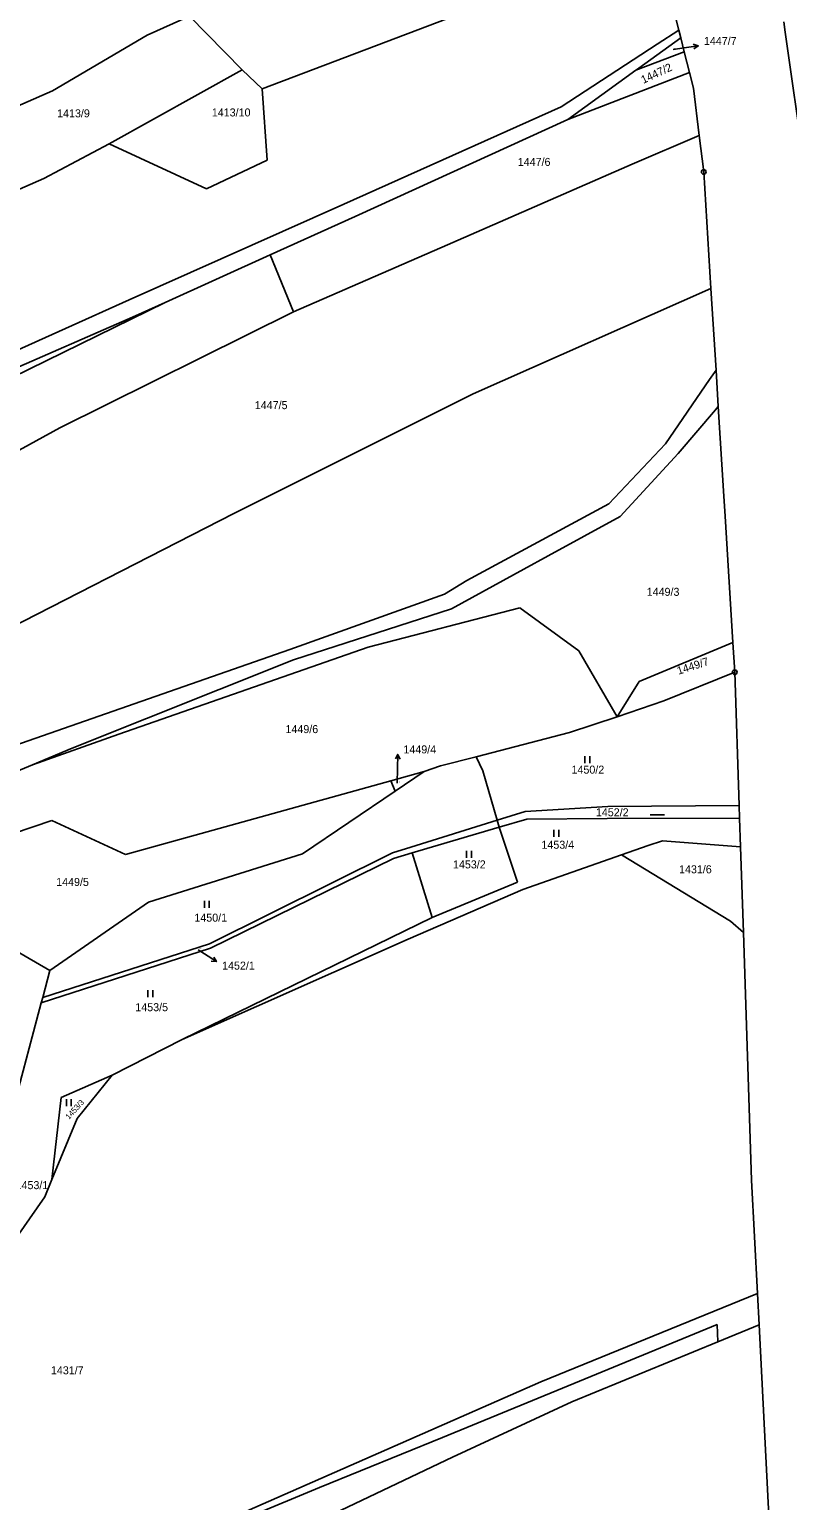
# Model space of a CAD drawing. Extents: x -736345 to -729997, y -1130177 to -1122501.
# Drawn here: x -733170.8 to -733009.7, y -1126646.3 to -1126333.8 of the extents above; entities that cross this region are included whole.
import ezdxf

# ---------------------------------------------------------------- set-up
doc = ezdxf.new("R2010")
doc.units = 0
for name, color, linetype in [('Vrstva 1', 7, 'Continuous'), ('Vrstva 16', 7, 'Continuous'), ('Vrstva 18', 7, 'Continuous'), ('Vrstva 25', 7, 'Continuous')]:
    doc.layers.add(name, color=color, linetype=linetype)

msp = doc.modelspace()

# ---------------------------------------------------------------- linework, layer by layer
at = {"layer": 'Vrstva 1'}
for points in [[(-733121.35, -1126346.41), (-733068.67, -1126326.4)], [(-733034.35, -1126327.79), (-733032.8, -1126333.97)], [(-733145.79, -1126335.01), (-733136.83, -1126331.03)], [(-733125.58, -1126342.42), (-733136.83, -1126331.03)], [(-733010.5, -1126332.18), (-733010.19, -1126334.39)], [(-733165.89, -1126346.85), (-733145.79, -1126335.01)], [(-733041.32, -1126342.06), (-733032.38, -1126335.61)], [(-733037.41, -1126336.98), (-733032.8, -1126333.97)], [(-733032.8, -1126333.97), (-733032.38, -1126335.61)], [(-733032.38, -1126335.61), (-733031.64, -1126338.58)], [(-733010.19, -1126334.39), (-733006.17, -1126362.59)], [(-733057.79, -1126350.28), (-733037.41, -1126336.98)], [(-733031.64, -1126338.58), (-733041.92, -1126342.49)], [(-733031.64, -1126338.58), (-733030.53, -1126342.98)], [(-733125.58, -1126342.42), (-733153.84, -1126358.12)], [(-733121.35, -1126346.41), (-733125.58, -1126342.42)], [(-733056.41, -1126352.95), (-733041.92, -1126342.49)], [(-733041.92, -1126342.49), (-733041.32, -1126342.06)], [(-733030.53, -1126342.98), (-733056.41, -1126352.95)], [(-733030.53, -1126342.98), (-733029.7, -1126346.27)], [(-733177.44, -1126351.89), (-733165.89, -1126346.85)], [(-733121.35, -1126346.41), (-733120.3, -1126361.6)], [(-733029.7, -1126346.27), (-733028.47, -1126356.36)], [(-733103.99, -1126370.97), (-733057.79, -1126350.28)], [(-733101.57, -1126373.55), (-733056.41, -1126352.95)], [(-733153.84, -1126358.12), (-733167.77, -1126365.45)], [(-733133.16, -1126367.65), (-733153.84, -1126358.12)], [(-733042.71, -1126362.41), (-733028.47, -1126356.36)], [(-733028.47, -1126356.36), (-733027.52, -1126364.1)], [(-733120.3, -1126361.6), (-733133.16, -1126367.65)], [(-733081.94, -1126379.54), (-733042.71, -1126362.41)], [(-733027.52, -1126364.1), (-733025.98, -1126388.84)], [(-733167.77, -1126365.45), (-733182.23, -1126371.81)], [(-733103.99, -1126370.97), (-733149.61, -1126391.25)], [(-733119.64, -1126381.73), (-733101.57, -1126373.55)], [(-733114.67, -1126393.81), (-733081.94, -1126379.54)], [(-733141.97, -1126391.83), (-733119.64, -1126381.73)], [(-733114.67, -1126393.81), (-733119.64, -1126381.73)], [(-733025.98, -1126388.84), (-733076.51, -1126411.23)], [(-733025.98, -1126388.84), (-733024.9, -1126406.2)], [(-733196.21, -1126418.34), (-733141.97, -1126391.83)], [(-733176.66, -1126403.45), (-733149.61, -1126391.25)], [(-733148.91, -1126394.97), (-733141.97, -1126391.83)], [(-733176.49, -1126406.98), (-733148.91, -1126394.97)], [(-733164.34, -1126418.42), (-733114.67, -1126393.81)], [(-733026.26, -1126408.18), (-733035.63, -1126421.83)], [(-733024.9, -1126406.2), (-733026.26, -1126408.18)], [(-733024.9, -1126406.2), (-733024.42, -1126413.94)], [(-733127.41, -1126436.66), (-733076.51, -1126411.23)], [(-733024.42, -1126413.94), (-733025.03, -1126414.65)], [(-733024.42, -1126413.94), (-733023.24, -1126432.98)], [(-733032.96, -1126423.87), (-733025.03, -1126414.65)], [(-733164.34, -1126418.42), (-733203.24, -1126439.78)], [(-733047.65, -1126434.58), (-733035.63, -1126421.83)], [(-733032.96, -1126423.87), (-733045.3, -1126437.27)], [(-733023.24, -1126432.98), (-733022.97, -1126437.18)], [(-733077.83, -1126450.86), (-733047.65, -1126434.58)], [(-733127.41, -1126436.66), (-733184.22, -1126465.69)], [(-733045.3, -1126437.27), (-733060.6, -1126445.64)], [(-733022.97, -1126437.18), (-733021.3, -1126464.03)], [(-733060.6, -1126445.64), (-733065.77, -1126448.47)], [(-733065.77, -1126448.47), (-733081.13, -1126456.87)], [(-733082.59, -1126453.8), (-733077.83, -1126450.86)], [(-733115.48, -1126465.55), (-733082.59, -1126453.8)], [(-733081.13, -1126456.87), (-733114.68, -1126467.7)], [(-733098.86, -1126465), (-733066.56, -1126456.66)], [(-733054.02, -1126465.84), (-733066.56, -1126456.66)], [(-733041.26, -1126472.34), (-733021.3, -1126464.03)], [(-733021.3, -1126464.03), (-733020.91, -1126470.35)], [(-733205.64, -1126496.99), (-733115.48, -1126465.55)], [(-733151.82, -1126483.55), (-733098.86, -1126465)], [(-733054.02, -1126465.84), (-733045.89, -1126479.8)], [(-733161.71, -1126486.5), (-733114.68, -1126467.7)], [(-733020.91, -1126470.35), (-733035.97, -1126476.47)], [(-733020.91, -1126470.35), (-733019.97, -1126498.64)], [(-733041.26, -1126472.34), (-733045.89, -1126479.8)], [(-733045.89, -1126479.8), (-733035.97, -1126476.47)], [(-733045.89, -1126479.8), (-733056.01, -1126483.19)], [(-733075.87, -1126488.31), (-733056.01, -1126483.19)], [(-733170.16, -1126490.01), (-733151.82, -1126483.55)], [(-733170.16, -1126490.01), (-733161.71, -1126486.5)], [(-733083.44, -1126490.26), (-733075.87, -1126488.31)], [(-733074.45, -1126491.3), (-733075.87, -1126488.31)], [(-733188.96, -1126497.83), (-733170.16, -1126490.01)], [(-733094, -1126493.45), (-733086.93, -1126491.44)], [(-733086.93, -1126491.44), (-733093.12, -1126495.63)], [(-733083.44, -1126490.26), (-733086.93, -1126491.44)], [(-733074.45, -1126491.3), (-733071.4, -1126501.78)], [(-733150.38, -1126509.06), (-733094, -1126493.45)], [(-733093.12, -1126495.63), (-733112.77, -1126508.95)], [(-733094, -1126493.45), (-733093.12, -1126495.63)], [(-733065.45, -1126499.92), (-733047.92, -1126498.88)], [(-733047.92, -1126498.88), (-733019.97, -1126498.64)], [(-733019.97, -1126498.64), (-733019.88, -1126501.36)], [(-733166.05, -1126501.84), (-733231.08, -1126523.87)], [(-733150.38, -1126509.06), (-733166.05, -1126501.84)], [(-733089.79, -1126507.51), (-733071.4, -1126501.78)], [(-733071.4, -1126501.78), (-733065.45, -1126499.92)], [(-733071.4, -1126501.78), (-733070.96, -1126503.29)], [(-733070.96, -1126503.29), (-733065.11, -1126501.57)], [(-733065.11, -1126501.57), (-733048.04, -1126501.46)], [(-733048.04, -1126501.46), (-733019.88, -1126501.36)], [(-733019.88, -1126501.36), (-733019.68, -1126507.43)], [(-733070.96, -1126503.29), (-733089.45, -1126508.73)], [(-733070.96, -1126503.29), (-733067.06, -1126514.93)], [(-733093.68, -1126508.74), (-733089.79, -1126507.51)], [(-733044.97, -1126509.13), (-733039.31, -1126507.14)], [(-733039.31, -1126507.14), (-733036.3, -1126506.2)], [(-733036.3, -1126506.2), (-733019.68, -1126507.43)], [(-733019.68, -1126507.43), (-733019.07, -1126525.67)], [(-733112.77, -1126508.95), (-733145.48, -1126519.2)], [(-733132.56, -1126528.02), (-733093.68, -1126508.74)], [(-733093.44, -1126509.92), (-733132.3, -1126529)], [(-733093.44, -1126509.92), (-733089.45, -1126508.73)], [(-733089.45, -1126508.73), (-733085.21, -1126522.44)], [(-733065.95, -1126516.53), (-733044.97, -1126509.13)], [(-733044.97, -1126509.13), (-733021.79, -1126523.27)], [(-733090.31, -1126527.08), (-733065.95, -1126516.53)], [(-733067.06, -1126514.93), (-733085.21, -1126522.44)], [(-733190.58, -1126519.8), (-733166.45, -1126533.72)], [(-733166.45, -1126533.72), (-733145.48, -1126519.2)], [(-733085.21, -1126522.44), (-733138.38, -1126548.37)], [(-733021.79, -1126523.27), (-733019.07, -1126525.67)], [(-733019.07, -1126525.67), (-733017.33, -1126578.25)], [(-733132.3, -1126529), (-733168.29, -1126540.59)], [(-733167.98, -1126539.44), (-733132.56, -1126528.02)], [(-733138.38, -1126548.37), (-733090.31, -1126527.08)], [(-733166.45, -1126533.72), (-733167.98, -1126539.44)], [(-733167.98, -1126539.44), (-733168.29, -1126540.59)], [(-733175.35, -1126567.06), (-733168.29, -1126540.59)], [(-733153.26, -1126555.96), (-733138.38, -1126548.37)], [(-733164.06, -1126560.66), (-733153.26, -1126555.96)], [(-733160.64, -1126565.13), (-733153.26, -1126555.96)], [(-733164.06, -1126560.66), (-733166.04, -1126578.1)], [(-733166.04, -1126578.1), (-733160.64, -1126565.13)], [(-733167.57, -1126581.77), (-733166.04, -1126578.1)], [(-733017.33, -1126578.25), (-733016.1, -1126602.33)], [(-733175.21, -1126592.75), (-733167.57, -1126581.77)], [(-733016.1, -1126602.33), (-733062.13, -1126621.06)], [(-733016.1, -1126602.33), (-733015.76, -1126608.98)], [(-733024.68, -1126608.89), (-733057.55, -1126622.44)], [(-733024.51, -1126612.58), (-733024.68, -1126608.89)], [(-733024.51, -1126612.58), (-733015.76, -1126608.98)], [(-733015.76, -1126608.98), (-733009.91, -1126723.63)], [(-733055.56, -1126625.36), (-733024.51, -1126612.58)], [(-733062.13, -1126621.06), (-733132.26, -1126651.9)], [(-733083.01, -1126632.9), (-733057.55, -1126622.44)], [(-733080.87, -1126637.12), (-733055.56, -1126625.36)], [(-733109.14, -1126643.51), (-733083.01, -1126632.9)], [(-733106.06, -1126649.09), (-733080.87, -1126637.12)], [(-733138.78, -1126655.85), (-733109.14, -1126643.51)]]:
    msp.add_lwpolyline(points, dxfattribs=at)
at = {"layer": 'Vrstva 16'}
for points in [[(-733033.98, -1126338.08), (-733031.64, -1126337.75)], [(-733092.65, -1126493.93), (-733092.59, -1126490.8)], [(-733134.92, -1126529.32), (-733133.58, -1126530.19)]]:
    msp.add_lwpolyline(points, dxfattribs=at)
at = {"layer": 'Vrstva 25'}
for points in [[(-733031.64, -1126337.75), (-733028.67, -1126337.328)], [(-733029.731, -1126336.974), (-733028.67, -1126337.328), (-733029.59, -1126337.963)], [(-733093.048, -1126488.79), (-733092.528, -1126487.801), (-733092.049, -1126488.811)], [(-733092.59, -1126490.8), (-733092.528, -1126487.801)], [(-733052.767, -1126489.665), (-733052.767, -1126488.165)], [(-733051.733, -1126489.665), (-733051.733, -1126488.165)], [(-733038.88, -1126500.65), (-733035.88, -1126500.65)], [(-733059.337, -1126505.315), (-733059.337, -1126503.815)], [(-733058.303, -1126505.315), (-733058.303, -1126503.815)], [(-733077.907, -1126509.795), (-733077.907, -1126508.295)], [(-733076.873, -1126509.795), (-733076.873, -1126508.295)], [(-733133.617, -1126520.395), (-733133.617, -1126518.895)], [(-733132.583, -1126520.395), (-733132.583, -1126518.895)], [(-733133.58, -1126530.19), (-733131.07, -1126531.832)], [(-733131.633, -1126530.866), (-733131.07, -1126531.832), (-733132.181, -1126531.703)], [(-733145.647, -1126539.415), (-733145.647, -1126537.915)], [(-733144.613, -1126539.415), (-733144.613, -1126537.915)], [(-733162.947, -1126562.545), (-733162.947, -1126561.045)], [(-733161.913, -1126562.545), (-733161.913, -1126561.045)]]:
    msp.add_lwpolyline(points, dxfattribs=at)
for centre, radius in [((-733027.52, -1126364.1), 0.5), ((-733027.52, -1126364.1), 0.032), ((-733020.91, -1126470.35), 0.5), ((-733020.91, -1126470.35), 0.032)]:
    msp.add_circle(centre, radius, dxfattribs=at)

# ---------------------------------------------------------------- texts
at = {"layer": 'Vrstva 16'}
for s, p in [('1447/7', (-733027.47, -1126337.12)), ('1449/4', (-733091.33, -1126487.6)), ('1452/1', (-733129.87, -1126533.53)), ('1453/1', (-733173.76, -1126580.16))]:
    msp.add_text(s, height=1.7, dxfattribs=at).set_placement(p)
at = {"layer": 'Vrstva 18'}
for s, height, p in [('1447/7', 0.1, (-733033.78, -1126337.88)), ('1413/9', 1.7, (-733164.93, -1126352.49)), ('1413/10', 1.7, (-733132.05, -1126352.3)), ('1447/6', 1.7, (-733067.03, -1126362.81)), ('1447/5', 1.7, (-733122.92, -1126414.48)), ('1449/3', 1.7, (-733039.63, -1126454.13)), ('1449/6', 1.7, (-733116.4, -1126483.29)), ('1450/2', 1.7, (-733055.61, -1126491.9)), ('1449/4', 0.1, (-733092.45, -1126493.73)), ('1452/2', 1.7, (-733050.43, -1126500.96)), ('1453/4', 1.7, (-733062, -1126507.85)), ('1453/2', 1.7, (-733080.8, -1126512.03)), ('1431/6', 1.7, (-733032.76, -1126513.07)), ('1449/5', 1.7, (-733165.13, -1126515.76)), ('1450/1', 1.7, (-733135.76, -1126523.34)), ('1452/1', 0.1, (-733134.72, -1126529.12)), ('1453/5', 1.7, (-733148.31, -1126542.36)), ('1431/7', 1.7, (-733166.25, -1126619.49))]:
    msp.add_text(s, height=height, dxfattribs=at).set_placement(p)
for s, height, rotation, p in [('1447/2', 1.7, 25.1002, (-733040.354, -1126345.395)), ('1449/7', 1.7, 18.00014, (-733032.882, -1126470.908)), ('1453/3', 1.2, 47.40038, (-733162.401, -1126565.428))]:
    msp.add_text(s, height=height, rotation=rotation, dxfattribs=at).set_placement(p)

doc.saveas('drawing.dxf')
